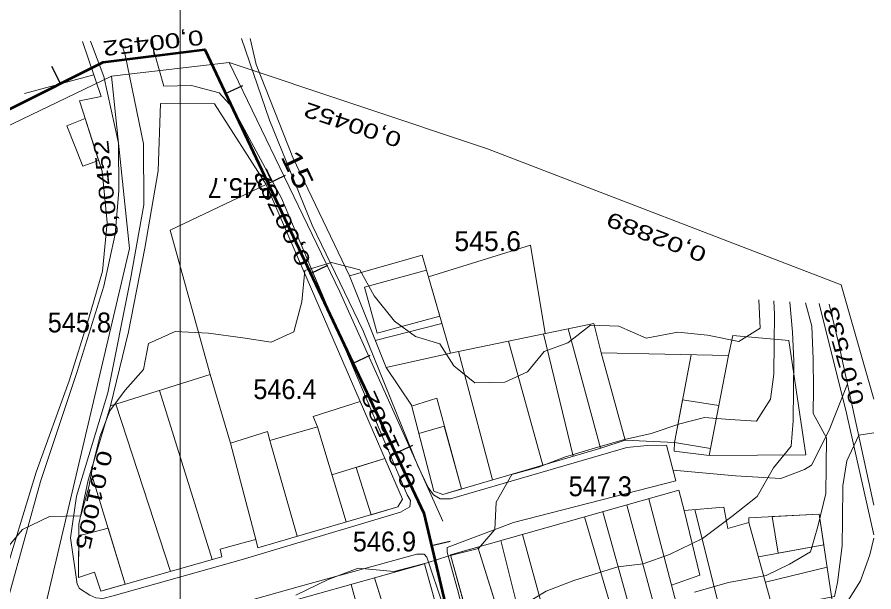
# Model space of a CAD drawing. Extents: x 949 to 2631, y -1701 to -513.
# Drawn here: x 1266.8 to 1439, y -798 to -682.4 of the extents above; entities that cross this region are included whole.
import ezdxf
from ezdxf.enums import TextEntityAlignment as Align

# ---------------------------------------------------------------- set-up
doc = ezdxf.new("R2010")
doc.units = 0
doc.header["$LTSCALE"] = 1.2
for name, color, linetype, lineweight in [('10', 7, 'Continuous', 13), ('11', 7, 'Continuous', 13), ('16', 7, 'Continuous', 13), ('17', 7, 'Continuous', 13), ('20', 7, 'Continuous', 13), ('21', 7, 'Continuous', 13), ('29', 7, 'Continuous', 25), ('3', 7, 'Continuous', 13), ('32', 7, 'Continuous', 13), ('34', 7, 'Continuous', 35), ('4', 7, 'Continuous', 13), ('5', 7, 'Continuous', 13), ('8', 7, 'Continuous', 13)]:
    doc.layers.add(name, color=color, linetype=linetype, lineweight=lineweight)
doc.layers.add('63', color=7, linetype='Continuous')

msp = doc.modelspace()

# ---------------------------------------------------------------- linework, layer by layer
at = {"layer": '10'}
for p, q in [((1282.152, -694.052), (1268.222, -697.802)), ((1338.762, -747.432), (1352.132, -744.012)), ((1384.042, -769.122), (1377.522, -745.092)), ((1378.522, -770.742), (1372.542, -746.132)), ((1365.522, -747.592), (1372.412, -772.522)), ((1353.852, -750.022), (1340.952, -752.902)), ((1355.512, -749.672), (1362.322, -775.472)), ((1389.002, -767.502), (1384.182, -749.942)), ((1398.882, -767.952), (1402.252, -750.332)), ((1409.732, -750.492), (1405.842, -770.612)), ((1295.352, -757.512), (1305.942, -791.522)), ((1297.602, -793.882), (1286.612, -760.282)), ((1327.132, -764.812), (1332.902, -783.952)), ((1323.032, -786.822), (1317.582, -767.562)), ((1309.662, -768.102), (1314.772, -787.462)), ((1330.052, -774.492), (1340.702, -771.212)), ((1337.912, -782.502), (1334.912, -772.992)), ((1281.542, -773.862), (1288.502, -796.472)), ((1402.982, -781.472), (1414.022, -825.712)), ((1380.812, -782.942), (1389.762, -813.272)), ((1392.852, -811.882), (1384.502, -781.892)), ((1379.922, -829.122), (1368.372, -786.452)), ((1370.352, -812.982), (1363.972, -787.702)), ((1415.772, -790.962), (1428.912, -788.572)), ((1359.382, -788.992), (1367.202, -814.062)), ((1429.572, -793.002), (1417.182, -796.042))]:
    msp.add_line(p, q, dxfattribs=at)
for points in [[(1333.562, -734.442), (1322.152, -710.672), (1314.792, -691.952), (1313.622, -686.702)], [(1263.552, -796.972), (1270.582, -773.952), (1277.212, -755.552), (1281.162, -742.942), (1283.902, -733.522), (1284.832, -723.762), (1283.832, -713.442), (1279.292, -699.272), (1283.622, -698.382), (1279.872, -687.332)], [(1285.522, -760.622), (1289.122, -745.712), (1292.452, -728.882), (1295.082, -713.342), (1295.552, -699.772), (1306.452, -699.892), (1316.832, -716.072), (1335.742, -759.732)], [(1316.832, -716.072), (1297.552, -725.292), (1305.562, -754.272)], [(1349.442, -734.652), (1369.962, -728.282), (1372.912, -746.052)], [(1346.042, -760.662), (1351.092, -759.042), (1356.062, -777.302)], [(1438.974, -805.651), (1436.752, -805.862), (1435.902, -799.902), (1430.662, -800.302), (1427.992, -782.402), (1413.842, -783.082), (1413.852, -784.032), (1409.632, -785.252), (1408.812, -780.982), (1400.862, -781.652), (1399.762, -777.582), (1353.892, -790.552), (1360.912, -816.232), (1365.092, -830.592), (1398.692, -827.262), (1438.974, -823.176)], [(1406.092, -826.512), (1406.122, -826.512), (1393.742, -779.282)], [(1389.302, -780.542), (1397.462, -810.662), (1401.642, -809.412)], [(1398.302, -796.662), (1403.982, -794.632), (1400.862, -781.652)], [(1413.852, -784.032), (1418.482, -800.752), (1421.602, -811.352), (1421.732, -812.222)], [(1351.992, -804.332), (1342.512, -807.622), (1338.622, -795.182)], [(1333.882, -796.512), (1340.912, -822.172), (1353.042, -818.472)]]:
    msp.add_lwpolyline(points, dxfattribs=at)
for points in [[(1333.562, -734.442), (1340.952, -752.902), (1346.002, -760.492), (1350.522, -777.772), (1352.302, -778.402), (1384.112, -769.102), (1389.002, -767.502), (1398.882, -767.952), (1398.862, -769.682), (1405.842, -770.612), (1425.272, -770.452), (1421.892, -747.472), (1410.592, -746.422), (1409.732, -750.492), (1384.182, -749.942), (1382.672, -744.022), (1353.852, -750.022), (1348.192, -730.302)], [(1285.522, -760.622), (1281.032, -775.552), (1279.172, -784.412), (1279.072, -795.082), (1282.292, -794.072), (1283.582, -797.862), (1307.932, -790.952), (1307.542, -789.422), (1312.902, -787.952), (1314.772, -787.462), (1315.132, -789.122), (1343.312, -780.932), (1344.222, -779.362), (1335.742, -759.732), (1326.242, -762.762), (1327.132, -764.812), (1317.582, -767.562), (1317.112, -765.742), (1309.662, -768.102), (1305.562, -754.272)], [(1261.072, -845.232), (1267.812, -827.642), (1269.922, -822.102), (1274.252, -818.022), (1279.762, -814.312), (1292.232, -808.992), (1320.002, -800.432), (1348.632, -792.352), (1351.992, -804.332), (1353.582, -825.712), (1335.712, -830.512), (1320.662, -833.722), (1320.662, -842.402), (1303.592, -845.722), (1302.402, -842.752), (1293.012, -844.962), (1278.902, -846.532)]]:
    msp.add_lwpolyline(points, close=True, dxfattribs=at)
at = {"layer": '11'}
for points in [[(1283.132, -711.272), (1280.442, -702.852), (1276.722, -704.322), (1279.942, -712.432)], [(1349.052, -733.322), (1336.602, -736.752), (1339.152, -745.992), (1351.702, -742.542)], [(1406.122, -769.162), (1407.792, -760.512), (1400.522, -759.382), (1398.882, -767.952)], [(1347.482, -766.182), (1350.522, -777.772), (1352.302, -778.402), (1356.062, -777.302), (1352.632, -764.682)], [(1337.912, -782.502), (1334.912, -772.992), (1340.702, -771.212), (1344.222, -779.362), (1343.312, -780.932)], [(1428.912, -788.572), (1419.722, -790.242), (1418.512, -782.862), (1427.992, -782.402)], [(1279.142, -786.762), (1279.072, -795.082), (1282.292, -794.072), (1283.582, -797.862), (1288.502, -796.472), (1285.032, -785.192)], [(1353.892, -790.552), (1357.072, -802.172), (1362.922, -800.342), (1359.382, -788.992)], [(1351.612, -802.972), (1342.042, -806.132), (1338.622, -795.182), (1348.632, -792.352)]]:
    msp.add_lwpolyline(points, close=True, dxfattribs=at)
at = {"layer": '16'}
msp.add_lwpolyline([(1398.602, -773.502), (1411.182, -774.702), (1420.292, -775.192), (1425.012, -773.392), (1426.422, -772.512), (1429.972, -765.512), (1433.672, -756.142)], dxfattribs=at)
at = {"layer": '17'}
msp.add_lwpolyline([(1438.974, -786.539), (1433.492, -762.102), (1428.002, -740.022)], dxfattribs=at)
at = {"layer": '20'}
for points in [[(1331.712, -746.692), (1319.882, -718.842), (1310.122, -700.702), (1307.372, -697.662), (1301.802, -696.192), (1296.232, -696.302), (1293.622, -687.082)], [(1336.322, -745.502), (1326.072, -724.272), (1317.522, -703.142), (1311.852, -686.732)], [(1265.162, -798.592), (1271.482, -775.802), (1278.842, -753.712), (1284.172, -736.542), (1286.492, -726.102), (1287.232, -717.382), (1287.112, -707.762), (1284.202, -694.352), (1281.522, -687.302)], [(1278.822, -796.482), (1277.472, -787.152), (1278.722, -778.772), (1285.012, -757.992), (1289.552, -735.122), (1292.222, -720.172), (1292.162, -707.892), (1288.492, -689.992), (1287.512, -687.192)]]:
    msp.add_lwpolyline(points, dxfattribs=at)
at = {"layer": '21'}
msp.add_line((1299.562, -912.671), (1299.562, -607.115), dxfattribs=at)
at = {"layer": '29'}
for p, q in [((1294.354, -690.205), (1293.884, -686.405)), ((1275.455, -695.796), (1273.737, -692.374)), ((1308.674, -697.788), (1312.137, -696.154)), ((1317.211, -715.875), (1320.673, -714.24)), ((1325.747, -733.961), (1329.21, -732.327)), ((1334.283, -752.048), (1337.746, -750.414)), ((1342.82, -770.135), (1346.282, -768.5)), ((1350.047, -788.68), (1353.773, -787.798))]:
    msp.add_line(p, q, dxfattribs=at)
at = {"layer": '29', "lineweight": 53}
msp.add_lwpolyline([(1073.88, -805.132), (1073.202, -806.436), (1075.81, -807.79), (1086.799, -786.637), (1101.557, -787.729), (1138.256, -763.647), (1228.052, -719.585), (1284.057, -691.479), (1304.502, -688.949), (1348.513, -782.198), (1360.795, -834.118)], dxfattribs=at)
at = {"layer": '29'}
msp.add_lwpolyline([(1086.799, -786.637), (1101.557, -787.729), (1138.256, -763.647), (1228.052, -719.585), (1284.057, -691.479), (1304.502, -688.949), (1348.513, -782.198), (1360.795, -834.118), (1364.521, -833.237)], dxfattribs=at)
at = {"layer": '32'}
for points in [[(1438.974, -759.256), (1432.401, -736.237), (1361.321, -708.887), (1309.391, -691.567), (1285.701, -694.297), (1228.032, -722.054)], [(1352.341, -783.787), (1331.641, -737.657), (1309.391, -691.567)], [(1254.721, -881.197), (1256.541, -845.637), (1271.121, -806.437), (1289.341, -728.947), (1285.701, -694.297)]]:
    msp.add_lwpolyline(points, dxfattribs=at)
at = {"layer": '4'}
msp.add_lwpolyline([(1438.974, -766.001), (1435.942, -766.492), (1433.562, -771.642), (1432.732, -776.712), (1432.682, -783.502), (1432.622, -788.752), (1431.632, -796.132), (1431.092, -798.932), (1424.442, -800.232), (1418.892, -800.472), (1412.482, -800.882), (1405.672, -802.742), (1398.042, -804.902), (1389.412, -807.172)], dxfattribs=at)
at = {"layer": '5'}
for points in [[(1415.832, -739.262), (1416.122, -744.982), (1411.852, -747.682), (1405.512, -746.362), (1399.572, -745.802), (1393.202, -746.982), (1387.722, -744.572), (1382.002, -744.372), (1377.442, -747.942), (1372.702, -749.702), (1369.382, -753.752), (1364.812, -755.812), (1358.742, -755.942), (1354.562, -752.552), (1351.712, -748.152), (1346.822, -746.642), (1342.592, -743.552), (1338.522, -738.502), (1335.642, -733.262), (1329.972, -731.742), (1324.592, -733.362), (1324.012, -739.692), (1322.402, -745.692), (1317.832, -747.812), (1312.132, -746.922), (1305.222, -746.002), (1298.542, -745.622), (1293.172, -748.032), (1292.172, -753.302), (1288.472, -757.442), (1285.382, -761.592), (1283.402, -766.832), (1282.092, -771.942), (1281.192, -776.882), (1279.572, -782.712), (1273.242, -782.842), (1267.822, -785.482), (1264.402, -789.572)], [(1418.862, -739.452), (1418.992, -742.252), (1418.922, -747.842), (1418.852, -754.202), (1418.202, -759.222), (1415.372, -763.702), (1410.042, -763.332), (1404.942, -762.972), (1399.992, -764.242), (1394.182, -766.162), (1388.832, -767.352), (1382.372, -769.262), (1376.812, -770.932), (1371.582, -772.942), (1366.182, -774.382), (1363.052, -779.962), (1362.812, -785.492), (1359.472, -789.312), (1353.322, -790.792), (1349.162, -792.192), (1342.532, -793.912), (1335.322, -793.262), (1329.252, -795.492), (1322.782, -798.662)], [(1422.102, -739.652), (1422.112, -739.742), (1422.622, -745.772), (1422.862, -751.542), (1422.822, -757.152), (1422.752, -763.642), (1422.382, -768.712), (1418.832, -773.062), (1415.522, -778.842), (1410.422, -782.842), (1404.552, -787.292), (1397.902, -790.472), (1392.592, -792.352), (1387.512, -792.962), (1378.692, -795.742), (1373.102, -797.892), (1368.652, -800.522)], [(1425.242, -739.852), (1426.492, -744.562), (1426.772, -751.202), (1426.832, -757.102), (1426.772, -762.152), (1429.422, -767.012), (1429.382, -772.852), (1429.312, -778.212), (1427.682, -784.832), (1426.212, -789.982), (1422.042, -792.442), (1417.352, -794.712), (1409.772, -796.122), (1402.902, -798.082)], [(1438.974, -787.198), (1438.192, -790.582), (1436.262, -795.792), (1433.322, -800.452)]]:
    msp.add_lwpolyline(points, dxfattribs=at)
at = {"layer": '8'}
for points in [[(1438.974, -780.541), (1431.892, -747.922), (1430.022, -740.152)], [(1336.322, -745.502), (1347.332, -772.682), (1349.352, -777.042), (1350.432, -778.482), (1351.772, -779.272), (1353.892, -779.292), (1389.292, -768.962), (1393.382, -768.602), (1397.262, -768.472), (1399.172, -775.642), (1366.552, -784.062), (1353.192, -789.082), (1353.182, -790.002), (1355.462, -798.272), (1360.132, -817.952), (1363.272, -828.742), (1363.812, -830.352), (1364.322, -831.052), (1365.312, -831.522), (1372.842, -831.172), (1410.152, -827.372), (1438.974, -824.574)], [(1331.712, -746.692), (1345.172, -778.472), (1345.822, -779.662), (1345.682, -780.902), (1343.832, -781.952), (1311.812, -791.562), (1286.072, -798.812), (1283.992, -799.302), (1282.572, -799.202), (1281.372, -798.652), (1279.322, -797.332), (1278.822, -796.482)], [(1352.392, -800.792), (1349.112, -791.032), (1348.612, -790.412), (1347.102, -790.442), (1323.742, -796.882), (1298.982, -803.842)]]:
    msp.add_lwpolyline(points, dxfattribs=at)

# ---------------------------------------------------------------- texts
at = {"layer": '3', "width": 0.95}
msp.add_text('545.7', height=4, rotation=180, dxfattribs=at).set_placement((1317.782, -714.812))
at = {"layer": '3'}
msp.add_text('545.6', height=4, dxfattribs=at).set_placement((1354.657, -729.474))
at = {"layer": '3', "width": 0.95}
for s, p in [('545.8', (1272.92, -745.833)), ('546.4', (1314.234, -759.247)), ('547.3', (1377.613, -778.773)), ('546.9', (1334.24, -789.873))]:
    msp.add_text(s, height=4, dxfattribs=at).set_placement(p)
at = {"layer": '34'}
for s, rotation, width, p in [('0,00452', 186.574, 1.4, (1304.018, -684.979)), ('0,00452', 161.555, 1.4, (1344.3, -705.9)), ('0,00452', 95.997, 1.35, (1287.098, -726.517)), ('0,00782', 115.769, 1.45, (1325.955, -731.565)), ('0,02889', 158.954, 1.45, (1405.62, -729.063)), ('0,07533', 105.937, 1.4, (1437.118, -759.907)), ('0,01582', 114.167, 1.45, (1347.127, -776.436)), ('0,01005', 256.769, 1.4, (1283.077, -769.335))]:
    msp.add_text(s, height=3, rotation=rotation, dxfattribs=dict(at, width=width)).set_placement(p)
at = {"layer": '63', "width": 1.3}
msp.add_text('15', height=4, rotation=295.266, dxfattribs=at).set_placement((1321.314, -713.951), align=Align.CENTER)

doc.saveas('drawing.dxf')
